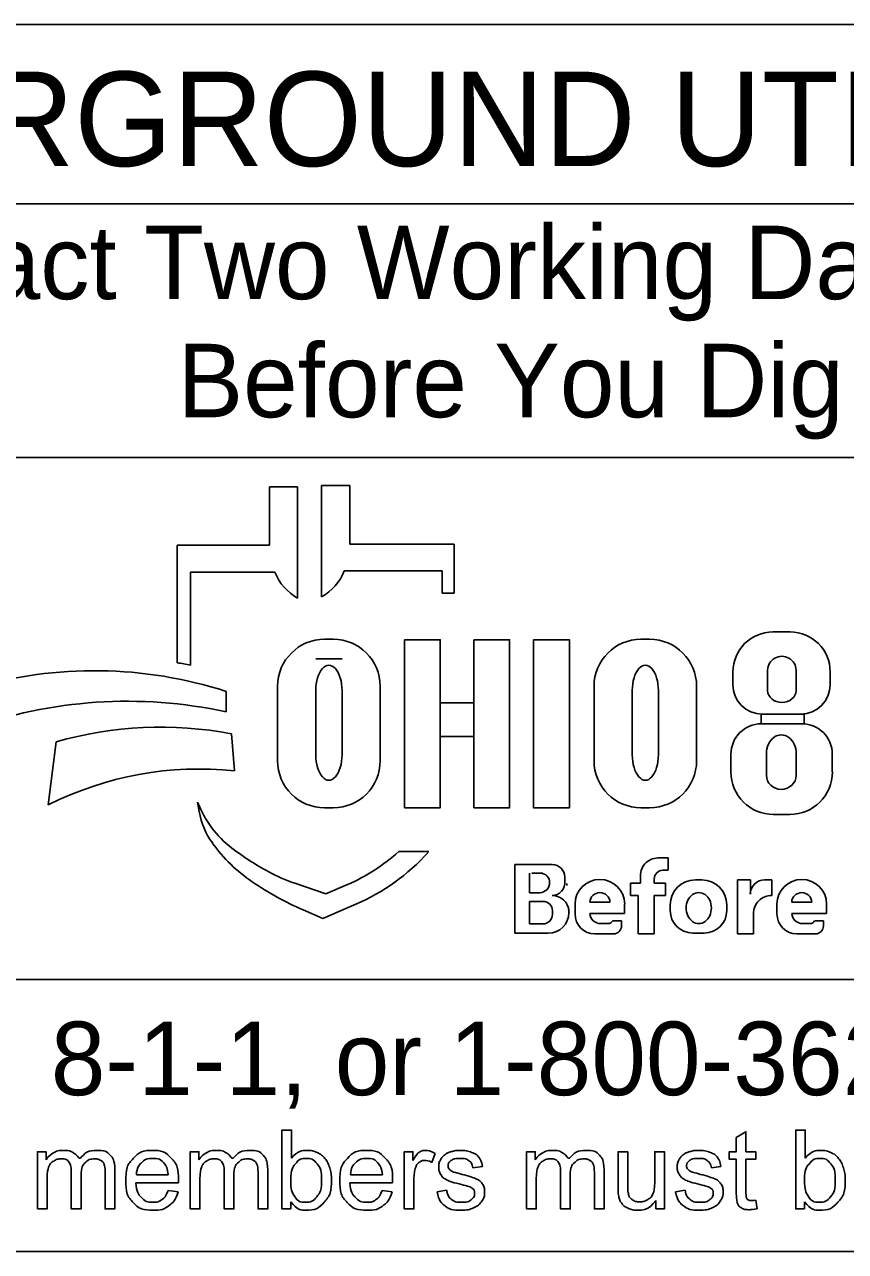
# Model space of a CAD drawing. Extents: x -12 to 164, y -741 to 24.
# Drawn here: x 3.89 to 5.455, y 2.143 to 4.48 of the extents above; entities that cross this region are included whole.
import ezdxf

# ---------------------------------------------------------------- set-up
doc = ezdxf.new("R2010")
doc.units = 0
doc.layers.add('SC_Scratch1', color=7, linetype='Continuous')
doc.layers.add('SH_Data', color=7, linetype='Continuous')

msp = doc.modelspace()

# ---------------------------------------------------------------- linework, layer by layer
at = {"layer": 'SC_Scratch1'}
for p, q in [((4.357, 3.4883), (4.357, 3.5998)), ((4.357, 3.5998), (4.4106, 3.5998)), ((4.4106, 3.5998), (4.4106, 3.3877)), ((4.4563, 3.39), (4.4563, 3.6021)), ((4.4563, 3.6021), (4.5099, 3.6021)), ((4.5099, 3.6021), (4.5099, 3.4906)), ((4.181, 3.2644), (4.181, 3.4883)), ((4.181, 3.4883), (4.357, 3.4883)), ((4.5099, 3.4906), (4.7092, 3.4906)), ((4.7092, 3.4906), (4.7092, 3.3968)), ((4.2063, 3.4369), (4.2063, 3.26)), ((4.3674, 3.4369), (4.2063, 3.4369)), ((4.6859, 3.4392), (4.4995, 3.4392)), ((4.6859, 3.3968), (4.6859, 3.4392)), ((4.7092, 3.3968), (4.6859, 3.3968)), ((5.3165, 3.3231), (5.3493, 3.3231)), ((4.462, 3.3091), (4.4785, 3.3091)), ((5.065, 3.3091), (5.0815, 3.3091)), ((4.4952, 3.2721), (4.4454, 3.2721)), ((5.3064, 3.2111), (5.3064, 3.2504)), ((5.3605, 3.2504), (5.3605, 3.2111)), ((5.2402, 3.2225), (5.2402, 3.2468)), ((5.4256, 3.2468), (5.4256, 3.2225)), ((4.2743, 3.2097), (4.2743, 3.1709)), ((4.3725, 3.0776), (4.3725, 3.2196)), ((4.4454, 3.089), (4.4454, 3.2114)), ((4.4952, 3.2114), (4.4952, 3.089)), ((4.568, 3.2196), (4.568, 3.0776)), ((4.9755, 3.0776), (4.9755, 3.2196)), ((5.0484, 3.089), (5.0484, 3.2114)), ((5.0982, 3.2114), (5.0982, 3.089)), ((5.171, 3.2196), (5.171, 3.0776)), ((5.3696, 3.1665), (5.2962, 3.1665)), ((5.2944, 3.1482), (5.3717, 3.1482)), ((3.9355, 2.9936), (3.9502, 3.1137)), ((4.2843, 3.1291), (4.2905, 3.0582)), ((5.2365, 3.0563), (5.2365, 3.0903)), ((5.304, 3.0503), (5.304, 3.0912)), ((5.3609, 3.0912), (5.3609, 3.0503)), ((5.4296, 3.0903), (5.4296, 3.0563)), ((4.2232, 2.9807), (4.2201, 2.9986)), ((4.4785, 2.9882), (4.462, 2.9882)), ((5.0815, 2.9882), (5.065, 2.9882)), ((5.3487, 2.9753), (5.3175, 2.9753)), ((4.6035, 2.9048), (4.6609, 2.9048)), ((4.8248, 2.749), (4.8248, 2.8798)), ((4.8248, 2.8798), (4.8959, 2.8798)), ((5.0973, 2.8926), (5.1168, 2.8926)), ((5.1168, 2.8926), (5.1168, 2.8696)), ((4.8527, 2.8263), (4.8527, 2.8632)), ((4.8779, 2.8632), (4.8567, 2.8632)), ((4.9197, 2.856), (4.9197, 2.8481)), ((5.0641, 2.8442), (5.0641, 2.8546)), ((5.0902, 2.8526), (5.0902, 2.8442)), ((5.1168, 2.8691), (5.1067, 2.8691)), ((4.405, 2.8444), (4.4645, 2.8239)), ((4.4645, 2.8239), (4.5055, 2.8417)), ((5.0447, 2.8212), (5.0447, 2.8442)), ((5.0447, 2.8442), (5.0641, 2.8442)), ((5.0902, 2.8442), (5.1117, 2.8442)), ((5.1117, 2.8442), (5.1117, 2.8212)), ((5.1686, 2.8508), (5.1807, 2.8508)), ((5.2488, 2.7478), (5.2488, 2.8505)), ((5.2488, 2.8505), (5.2734, 2.8505)), ((5.2734, 2.8505), (5.2734, 2.8237)), ((5.3006, 2.8505), (5.3145, 2.8505)), ((5.3145, 2.8505), (5.3145, 2.8209)), ((4.8721, 2.8263), (4.8527, 2.8263)), ((4.8527, 2.7669), (4.8527, 2.8097)), ((4.8527, 2.8097), (4.8783, 2.8097)), ((5.0059, 2.8082), (4.9674, 2.8082)), ((5.0597, 2.8212), (5.0447, 2.8212)), ((5.0597, 2.7478), (5.0597, 2.8212)), ((5.1117, 2.8212), (5.0902, 2.8212)), ((5.0902, 2.8212), (5.0902, 2.7478)), ((5.3908, 2.8082), (5.3523, 2.8082)), ((4.4584, 2.7769), (4.4211, 2.7934)), ((4.5217, 2.8044), (4.4584, 2.7769)), ((4.8964, 2.7916), (4.8964, 2.7853)), ((4.9278, 2.7887), (4.9278, 2.7884)), ((4.9393, 2.7858), (4.9393, 2.8042)), ((5.0338, 2.7866), (4.9674, 2.7866)), ((5.0338, 2.8042), (5.0338, 2.7866)), ((5.1207, 2.7922), (5.1207, 2.8029)), ((5.2285, 2.8029), (5.2285, 2.7922)), ((5.2793, 2.786), (5.2793, 2.7478)), ((5.3242, 2.7858), (5.3242, 2.8042)), ((5.4188, 2.7866), (5.3523, 2.7866)), ((5.4188, 2.8042), (5.4188, 2.7866)), ((4.878, 2.7669), (4.8527, 2.7669)), ((4.9883, 2.7673), (5.0025, 2.7673)), ((5.011, 2.7729), (5.0279, 2.7729)), ((5.0279, 2.7729), (5.0279, 2.7631)), ((5.3733, 2.7673), (5.3874, 2.7673)), ((5.396, 2.7729), (5.4128, 2.7729)), ((5.4128, 2.7729), (5.4128, 2.7631)), ((4.8884, 2.749), (4.8248, 2.749)), ((5.0127, 2.7478), (4.9773, 2.7478)), ((5.0902, 2.7478), (5.0597, 2.7478)), ((5.1857, 2.7494), (5.1635, 2.7494)), ((5.2793, 2.7478), (5.2488, 2.7478)), ((5.3976, 2.7478), (5.3622, 2.7478))]:
    msp.add_line(p, q, dxfattribs=at)
for points in [[(4.6144, 3.3081), (4.6824, 3.3081), (4.6824, 2.9881), (4.6144, 2.9881)], [(4.7465, 3.3081), (4.8145, 3.3081), (4.8145, 2.9881), (4.7465, 2.9881)], [(4.8599, 3.3081), (4.9286, 3.3081), (4.9286, 2.9881), (4.8599, 2.9881)], [(4.6824, 3.1882), (4.7465, 3.1882), (4.7465, 3.1242), (4.6824, 3.1242)], [(5.2941, 3.1665), (5.3758, 3.1665), (5.3758, 3.1481), (5.2941, 3.1481)]]:
    msp.add_lwpolyline(points, close=True, dxfattribs=at)
for points in [[(4.3978, 2.2239), (4.3807, 2.2239), (4.3807, 2.3741), (4.3991, 2.3741), (4.3991, 2.3206)], [(5.2467, 2.2558), (5.2467, 2.3185), (5.2331, 2.3185), (5.2331, 2.3328), (5.2467, 2.3328), (5.2467, 2.3597), (5.2651, 2.3708), (5.2651, 2.3328), (5.2836, 2.3328), (5.2836, 2.3185), (5.2651, 2.3185), (5.2651, 2.2547)], [(5.3768, 2.2239), (5.3598, 2.2239), (5.3598, 2.3741), (5.3782, 2.3741), (5.3782, 2.3206)], [(3.9147, 2.2239), (3.9147, 2.3328), (3.9312, 2.3328), (3.9312, 2.3174)], [(4.2061, 2.2239), (4.2061, 2.3328), (4.2225, 2.3328), (4.2225, 2.3174)], [(4.6138, 2.2239), (4.6138, 2.3328), (4.6304, 2.3328), (4.6304, 2.3163)], [(4.6729, 2.3293), (4.6664, 2.3122)], [(4.8471, 2.2239), (4.8471, 2.3328), (4.8635, 2.3328), (4.8635, 2.3174)], [(5.0214, 2.2654), (5.0214, 2.3328), (5.0398, 2.3328), (5.0398, 2.2724)], [(5.0911, 2.2745), (5.0911, 2.3328), (5.1095, 2.3328), (5.1095, 2.2239), (5.093, 2.2239)], [(3.9978, 2.2871), (3.9978, 2.2239), (3.9793, 2.2239), (3.9793, 2.2946)], [(4.0622, 2.2986), (4.0622, 2.2239), (4.0438, 2.2239), (4.0438, 2.2924)], [(4.2891, 2.2871), (4.2891, 2.2239), (4.2707, 2.2239), (4.2707, 2.2946)], [(4.3536, 2.2986), (4.3536, 2.2239), (4.3351, 2.2239), (4.3351, 2.2924)], [(4.7628, 2.3046), (4.7448, 2.3022)], [(4.9301, 2.2871), (4.9301, 2.2239), (4.9117, 2.2239), (4.9117, 2.2946)], [(4.9946, 2.2986), (4.9946, 2.2239), (4.9761, 2.2239), (4.9761, 2.2924)], [(5.2174, 2.3046), (5.1993, 2.3022)], [(3.9331, 2.2803), (3.9331, 2.2239), (3.9147, 2.2239)], [(4.1834, 2.2736), (4.1023, 2.2736)], [(4.1033, 2.2887), (4.1641, 2.2887)], [(4.2245, 2.2803), (4.2245, 2.2239), (4.2061, 2.2239)], [(4.5914, 2.2736), (4.5103, 2.2736)], [(4.5113, 2.2887), (4.5721, 2.2887)], [(4.6323, 2.2809), (4.6323, 2.2239), (4.6138, 2.2239)], [(4.8655, 2.2803), (4.8655, 2.2239), (4.8471, 2.2239)], [(4.1639, 2.2591), (4.1829, 2.2567)], [(4.5719, 2.2591), (4.5909, 2.2567)], [(4.6764, 2.2564), (4.6946, 2.2593)], [(5.131, 2.2564), (5.1492, 2.2593)], [(4.3978, 2.2375), (4.3978, 2.2239)], [(5.093, 2.2239), (5.093, 2.24)], [(5.2836, 2.2404), (5.2862, 2.2241)], [(5.3768, 2.2375), (5.3768, 2.2239)]]:
    msp.add_lwpolyline(points, dxfattribs=at)
for centre, radius, start, end in [((4.4587, 3.4736), 0.0985, 201.9296, 240.7469), ((4.4082, 3.476), 0.0985, 299.2531, 338.0704), ((5.3165, 3.2468), 0.0763, 90, 180), ((5.3493, 3.2468), 0.0763, 0, 90), ((4.462, 3.2196), 0.0895, 90, 180), ((4.4785, 3.2196), 0.0895, 0, 90), ((5.065, 3.2196), 0.0895, 90, 180), ((5.0815, 3.2196), 0.0895, 0, 90), ((4.0231, 2.4302), 0.8191, 72.1402, 106.3144), ((4.0529, 2.4554), 0.8191, 79.2074, 81.0007), ((5.2962, 3.2225), 0.056, 180, 270), ((5.3696, 3.2225), 0.056, 270, 0), ((4.0862, 2.2991), 0.8919, 77.8238, 109.8274), ((4.1501, 2.4094), 0.7322, 79.44, 105.8467), ((5.2944, 3.0903), 0.0579, 90, 180), ((5.3717, 3.0903), 0.0579, 0, 90), ((4.462, 3.0776), 0.0895, 180, 270), ((4.4785, 3.0776), 0.0895, 270, 0), ((5.065, 3.0776), 0.0895, 180, 270), ((5.0815, 3.0776), 0.0895, 270, 0), ((4.2221, 2.4262), 0.6357, 83.8248, 116.8021), ((5.3175, 3.0563), 0.081, 180, 270), ((5.3487, 3.0563), 0.081, 270, 0), ((4.4075, 3.0707), 0.2008, 201.0457, 232.5314), ((4.3645, 3.0048), 0.1433, 189.6817, 216.0884), ((4.4981, 3.1022), 0.3088, 216.0884, 235.7167), ((4.6001, 3.3219), 0.5173, 232.5314, 241.794), ((4.3621, 3.1722), 0.3602, 293.4582, 312.0712), ((4.3621, 3.1722), 0.401, 293.4582, 317.8286), ((4.8959, 2.856), 0.0238, 0, 90), ((5.0973, 2.859), 0.0335, 90, 187.5187), ((4.5149, 3.1631), 0.3371, 241.794, 250.9821), ((4.874, 2.8463), 0.0169, 357.8325, 90), ((5.1067, 2.8526), 0.0165, 90, 180), ((4.6647, 3.3465), 0.6044, 235.7167, 246.2325), ((4.8721, 2.845), 0.0187, 270, 2.0582), ((4.8955, 2.8453), 0.0243, 270, 6.6529), ((4.9061, 2.8438), 0.0175, 347.4023, 0), ((4.9866, 2.8042), 0.0473, 0, 180), ((5.1686, 2.8029), 0.0478, 90, 180), ((5.1807, 2.8029), 0.0478, 0, 90), ((5.3002, 2.8237), 0.0269, 89.2449, 180), ((5.3715, 2.8042), 0.0473, 0, 180), ((4.8783, 2.7916), 0.0181, 0, 90), ((4.8957, 2.7889), 0.0321, 4.0748, 90), ((4.9866, 2.8072), 0.0193, 2.9632, 177.0368), ((5.3142, 2.786), 0.0349, 89.6033, 180), ((5.3715, 2.8072), 0.0193, 2.9632, 177.0368), ((4.878, 2.7853), 0.0184, 270, 0), ((4.8884, 2.7884), 0.0393, 270, 0), ((4.8948, 2.7887), 0.033, 0, 11.7502), ((4.9773, 2.7858), 0.038, 180, 270), ((4.9883, 2.7883), 0.021, 184.827, 270), ((5.1635, 2.7922), 0.0428, 180, 270), ((5.1857, 2.7922), 0.0428, 270, 0), ((5.3622, 2.7858), 0.038, 180, 270), ((5.3733, 2.7883), 0.021, 184.827, 270), ((5.0025, 2.7767), 0.00938, 270, 335.9979), ((5.0127, 2.7631), 0.0152, 270, 0), ((5.3874, 2.7767), 0.00938, 270, 335.9979), ((5.3976, 2.7631), 0.0152, 270, 0)]:
    msp.add_arc(centre, radius, start, end, dxfattribs=at)
for centre, major_axis, ratio, start_param, end_param in [((5.3335, 3.2504), (0.0271, 0), 0.969373, 0, 3.141593), ((4.4703, 3.2114), (0, 0.0484), 0.514403, 4.712389, 7.853982), ((5.0733, 3.2114), (0, 0.0484), 0.514403, 4.712389, 7.853982), ((5.3335, 3.2111), (0.0271, 0), 0.818453, 3.141593, 6.283185), ((5.3324, 3.0912), (0, 0.0358), 0.794529, 4.712389, 7.853982), ((4.4703, 3.089), (0, 0.0484), 0.514403, 1.570796, 4.712389), ((5.0733, 3.089), (0, 0.0484), 0.514403, 1.570796, 4.712389), ((5.3324, 3.0503), (0.0284, 0), 0.959837, 3.141593, 6.283185), ((5.1751, 2.7976), (0, 0.029), 0.832186, 4.712389, 7.853982), ((5.1751, 2.7976), (0, 0.0302), 0.797287, 1.570796, 4.712389)]:
    msp.add_ellipse(centre, major_axis=major_axis, ratio=ratio, start_param=start_param, end_param=end_param, dxfattribs=at)
for points in [[(3.9312, 2.3174), (3.9363, 2.3254), (3.9448, 2.3303), (3.9533, 2.3352), (3.9642, 2.3352), (3.9763, 2.3352), (3.984, 2.3301), (3.9917, 2.3251), (3.9949, 2.3161), (4.0078, 2.3352), (4.0286, 2.3352), (4.0448, 2.3352), (4.0535, 2.3262), (4.0622, 2.3172), (4.0622, 2.2986)], [(3.9793, 2.2946), (3.9793, 2.3069), (3.9748, 2.313), (3.9703, 2.3191), (3.9601, 2.3191), (3.9523, 2.3191), (3.9457, 2.315), (3.9391, 2.311), (3.9361, 2.3031), (3.9331, 2.2952), (3.9331, 2.2803)], [(4.0438, 2.2924), (4.0438, 2.3035), (4.042, 2.3083), (4.0402, 2.3132), (4.0355, 2.3162), (4.0308, 2.3191), (4.0244, 2.3191), (4.0129, 2.3191), (4.0054, 2.3115), (3.9978, 2.3039), (3.9978, 2.2871)], [(4.1829, 2.2567), (4.1784, 2.24), (4.1662, 2.2307), (4.154, 2.2215), (4.1351, 2.2215), (4.1112, 2.2215), (4.0973, 2.2362), (4.0833, 2.2509), (4.0833, 2.2774), (4.0833, 2.3049), (4.0974, 2.32), (4.1115, 2.3352), (4.1341, 2.3352), (4.1559, 2.3352), (4.1697, 2.3203), (4.1835, 2.3055), (4.1835, 2.2785), (4.1835, 2.2769), (4.1834, 2.2736)], [(4.1641, 2.2887), (4.1628, 2.3025), (4.1571, 2.3094), (4.1483, 2.3201), (4.1343, 2.3201), (4.1215, 2.3201), (4.1129, 2.3115), (4.1042, 2.303), (4.1033, 2.2887)], [(4.2225, 2.3174), (4.2277, 2.3254), (4.2362, 2.3303), (4.2447, 2.3352), (4.2555, 2.3352), (4.2676, 2.3352), (4.2754, 2.3301), (4.2831, 2.3251), (4.2863, 2.3161), (4.2992, 2.3352), (4.3199, 2.3352), (4.3361, 2.3352), (4.3449, 2.3262), (4.3536, 2.3172), (4.3536, 2.2986)], [(4.2707, 2.2946), (4.2707, 2.3069), (4.2662, 2.313), (4.2617, 2.3191), (4.2514, 2.3191), (4.2437, 2.3191), (4.237, 2.315), (4.2304, 2.311), (4.2275, 2.3031), (4.2245, 2.2952), (4.2245, 2.2803)], [(4.3351, 2.2924), (4.3351, 2.3035), (4.3334, 2.3083), (4.3316, 2.3132), (4.3268, 2.3162), (4.3221, 2.3191), (4.3158, 2.3191), (4.3043, 2.3191), (4.2967, 2.3115), (4.2891, 2.3039), (4.2891, 2.2871)], [(4.3975, 2.2792), (4.3975, 2.2596), (4.4029, 2.2509), (4.4115, 2.2366), (4.4264, 2.2366), (4.4384, 2.2366), (4.4472, 2.2471), (4.456, 2.2576), (4.456, 2.2784), (4.456, 2.2998), (4.4476, 2.3099), (4.4392, 2.3201), (4.4272, 2.3201), (4.4151, 2.3201), (4.4063, 2.3096), (4.3975, 2.299), (4.3975, 2.2792)], [(4.3991, 2.3206), (4.4108, 2.3352), (4.4289, 2.3352), (4.439, 2.3352), (4.4479, 2.3311), (4.4569, 2.3271), (4.4627, 2.3198), (4.4685, 2.3124), (4.4717, 2.3021), (4.475, 2.2918), (4.475, 2.28), (4.475, 2.252), (4.4612, 2.2368), (4.4474, 2.2215), (4.428, 2.2215), (4.4087, 2.2215), (4.3978, 2.2375)], [(4.5909, 2.2567), (4.5864, 2.24), (4.5742, 2.2307), (4.562, 2.2215), (4.5431, 2.2215), (4.5192, 2.2215), (4.5052, 2.2362), (4.4913, 2.2509), (4.4913, 2.2774), (4.4913, 2.3049), (4.5054, 2.32), (4.5195, 2.3352), (4.5421, 2.3352), (4.5639, 2.3352), (4.5777, 2.3203), (4.5915, 2.3055), (4.5915, 2.2785), (4.5915, 2.2769), (4.5914, 2.2736)], [(4.5721, 2.2887), (4.5708, 2.3025), (4.5651, 2.3094), (4.5563, 2.3201), (4.5422, 2.3201), (4.5295, 2.3201), (4.5209, 2.3115), (4.5122, 2.303), (4.5113, 2.2887)], [(4.6304, 2.3163), (4.6368, 2.3278), (4.6421, 2.3315), (4.6475, 2.3352), (4.654, 2.3352), (4.6633, 2.3352), (4.6729, 2.3293)], [(4.6664, 2.3122), (4.6597, 2.3162), (4.653, 2.3162), (4.647, 2.3162), (4.6422, 2.3125), (4.6374, 2.3089), (4.6353, 2.3024), (4.6323, 2.2926), (4.6323, 2.2809)], [(4.7448, 2.3022), (4.7435, 2.3106), (4.7376, 2.3153), (4.7317, 2.3201), (4.721, 2.3201), (4.7083, 2.3201), (4.7028, 2.3159), (4.6974, 2.3116), (4.6974, 2.306), (4.6974, 2.3024), (4.6996, 2.2995), (4.7019, 2.2966), (4.7067, 2.2946), (4.7095, 2.2936), (4.723, 2.2899), (4.7426, 2.2847), (4.7504, 2.2813), (4.7581, 2.278), (4.7625, 2.2717), (4.767, 2.2653), (4.767, 2.2559), (4.767, 2.2467), (4.7616, 2.2386), (4.7562, 2.2304), (4.746, 2.226), (4.7359, 2.2215), (4.723, 2.2215), (4.7018, 2.2215), (4.6907, 2.2303), (4.6795, 2.2391), (4.6764, 2.2564)], [(4.6946, 2.2593), (4.6962, 2.2483), (4.7032, 2.2425), (4.7103, 2.2366), (4.7229, 2.2366), (4.7356, 2.2366), (4.7418, 2.2418), (4.748, 2.247), (4.748, 2.254), (4.748, 2.2602), (4.7425, 2.2638), (4.7387, 2.2663), (4.7236, 2.2701), (4.7033, 2.2752), (4.6955, 2.2789), (4.6876, 2.2827), (4.6836, 2.2893), (4.6795, 2.2959), (4.6795, 2.3038), (4.6795, 2.3111), (4.6829, 2.3173), (4.6862, 2.3235), (4.6919, 2.3276), (4.6963, 2.3308), (4.7037, 2.333), (4.7111, 2.3352), (4.7196, 2.3352), (4.7325, 2.3352), (4.7422, 2.3315), (4.7519, 2.3278), (4.7565, 2.3215), (4.7611, 2.3152), (4.7628, 2.3046)], [(4.8635, 2.3174), (4.8687, 2.3254), (4.8772, 2.3303), (4.8857, 2.3352), (4.8965, 2.3352), (4.9086, 2.3352), (4.9164, 2.3301), (4.9241, 2.3251), (4.9273, 2.3161), (4.9402, 2.3352), (4.9609, 2.3352), (4.9771, 2.3352), (4.9859, 2.3262), (4.9946, 2.3172), (4.9946, 2.2986)], [(4.9117, 2.2946), (4.9117, 2.3069), (4.9072, 2.313), (4.9027, 2.3191), (4.8924, 2.3191), (4.8847, 2.3191), (4.878, 2.315), (4.8714, 2.311), (4.8685, 2.3031), (4.8655, 2.2952), (4.8655, 2.2803)], [(4.9761, 2.2924), (4.9761, 2.3035), (4.9744, 2.3083), (4.9726, 2.3132), (4.9678, 2.3162), (4.9631, 2.3191), (4.9568, 2.3191), (4.9453, 2.3191), (4.9377, 2.3115), (4.9301, 2.3039), (4.9301, 2.2871)], [(5.1993, 2.3022), (5.1981, 2.3106), (5.1922, 2.3153), (5.1863, 2.3201), (5.1755, 2.3201), (5.1628, 2.3201), (5.1574, 2.3159), (5.152, 2.3116), (5.152, 2.306), (5.152, 2.3024), (5.1542, 2.2995), (5.1565, 2.2966), (5.1613, 2.2946), (5.1641, 2.2936), (5.1776, 2.2899), (5.1972, 2.2847), (5.2049, 2.2813), (5.2127, 2.278), (5.2171, 2.2717), (5.2215, 2.2653), (5.2215, 2.2559), (5.2215, 2.2467), (5.2161, 2.2386), (5.2108, 2.2304), (5.2006, 2.226), (5.1904, 2.2215), (5.1776, 2.2215), (5.1564, 2.2215), (5.1452, 2.2303), (5.1341, 2.2391), (5.131, 2.2564)], [(5.1492, 2.2593), (5.1507, 2.2483), (5.1578, 2.2425), (5.1648, 2.2366), (5.1775, 2.2366), (5.1902, 2.2366), (5.1964, 2.2418), (5.2025, 2.247), (5.2025, 2.254), (5.2025, 2.2602), (5.1971, 2.2638), (5.1933, 2.2663), (5.1782, 2.2701), (5.1579, 2.2752), (5.1501, 2.2789), (5.1422, 2.2827), (5.1382, 2.2893), (5.1341, 2.2959), (5.1341, 2.3038), (5.1341, 2.3111), (5.1374, 2.3173), (5.1408, 2.3235), (5.1465, 2.3276), (5.1508, 2.3308), (5.1583, 2.333), (5.1657, 2.3352), (5.1742, 2.3352), (5.187, 2.3352), (5.1967, 2.3315), (5.2064, 2.3278), (5.2111, 2.3215), (5.2157, 2.3152), (5.2174, 2.3046)], [(5.3766, 2.2792), (5.3766, 2.2596), (5.3819, 2.2509), (5.3906, 2.2366), (5.4054, 2.2366), (5.4175, 2.2366), (5.4263, 2.2471), (5.4351, 2.2576), (5.4351, 2.2784), (5.4351, 2.2998), (5.4267, 2.3099), (5.4182, 2.3201), (5.4063, 2.3201), (5.3942, 2.3201), (5.3854, 2.3096), (5.3766, 2.299), (5.3766, 2.2792)], [(5.3782, 2.3206), (5.3899, 2.3352), (5.408, 2.3352), (5.418, 2.3352), (5.427, 2.3311), (5.436, 2.3271), (5.4417, 2.3198), (5.4475, 2.3124), (5.4508, 2.3021), (5.4541, 2.2918), (5.4541, 2.28), (5.4541, 2.252), (5.4403, 2.2368), (5.4264, 2.2215), (5.4071, 2.2215), (5.3878, 2.2215), (5.3768, 2.2375)], [(4.1023, 2.2736), (4.1033, 2.2557), (4.1124, 2.2462), (4.1215, 2.2366), (4.1352, 2.2366), (4.1453, 2.2366), (4.1525, 2.242), (4.1597, 2.2473), (4.1639, 2.2591)], [(4.5103, 2.2736), (4.5113, 2.2557), (4.5204, 2.2462), (4.5295, 2.2366), (4.5432, 2.2366), (4.5533, 2.2366), (4.5605, 2.242), (4.5677, 2.2473), (4.5719, 2.2591)], [(5.0398, 2.2724), (5.0398, 2.258), (5.0409, 2.253), (5.0427, 2.2457), (5.0483, 2.2416), (5.0539, 2.2374), (5.0622, 2.2374), (5.0705, 2.2374), (5.0778, 2.2417), (5.085, 2.2459), (5.088, 2.2533), (5.0911, 2.2606), (5.0911, 2.2745)], [(5.093, 2.24), (5.0803, 2.2215), (5.0585, 2.2215), (5.0489, 2.2215), (5.0406, 2.2252), (5.0322, 2.2289), (5.0282, 2.2345), (5.0241, 2.2401), (5.0225, 2.2482), (5.0214, 2.2536), (5.0214, 2.2654)], [(5.2862, 2.2241), (5.2784, 2.2224), (5.2723, 2.2224), (5.2623, 2.2224), (5.2567, 2.2256), (5.2512, 2.2288), (5.249, 2.234), (5.2467, 2.2392), (5.2467, 2.2558)], [(5.2651, 2.2547), (5.2651, 2.2468), (5.2661, 2.2445), (5.2671, 2.2423), (5.2693, 2.2409), (5.2714, 2.2396), (5.2755, 2.2396), (5.2786, 2.2396), (5.2836, 2.2404)]]:
    msp.add_open_spline(points, degree=3, dxfattribs=at)
at = {"layer": 'SH_Data'}
for p, q in [((7.2509, 4.4803), (3.0009, 4.4803)), ((3.0009, 4.1387), (7.2509, 4.1387)), ((3.0009, 3.6553), (7.2509, 3.6553)), ((7.2509, 2.6607), (3.0009, 2.6607)), ((7.2509, 2.1428), (3.0009, 2.1428))]:
    msp.add_line(p, q, dxfattribs=at)

# ---------------------------------------------------------------- texts
at = {"layer": 'SC_Scratch1'}
for s, height, p in [('UNDERGROUND UTILITIES', 0.18, (3.1291, 4.2106)), ('Contact Two Working Days', 0.14, (3.4206, 3.9571)), ('Before You Dig', 0.14, (4.1818, 3.7321)), ('OHIO811, 8-1-1, or 1-800-362-2764', 0.14, (3.0454, 2.4406))]:
    msp.add_text(s, height=height, dxfattribs=at).set_placement(p)

doc.saveas('drawing.dxf')
